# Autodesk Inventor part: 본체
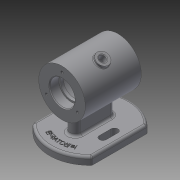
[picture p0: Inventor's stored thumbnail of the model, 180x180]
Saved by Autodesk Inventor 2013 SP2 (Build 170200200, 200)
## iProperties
Created: 2022-02
Part Number: 본체
Material: Generic
Document SubType Name: Modeling
Designer: a
Density: 1 g/cm^3
Mass: 183.424 g
Surface Area: 489.745 cm^2
Volume: 183.424 cm^3
Author: a
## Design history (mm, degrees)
sketch "스케치1"
  geometry: L1 (-36, 0)-(36, 0); L2 (-36, 16)-(-36, 30); L3 (-36, 30)-(36, 30); L4 (36, 30)-(36, 16); L5 (36, 16)-(24, 16); L6 (24, 16)-(24, 14); L7 (24, 14)-(20, 14); L8 (20, 14)-(20, 25); L9 (20, 25)-(-20, 25); L10 (-20, 25)-(-20, 14); L11 (-20, 14)-(-24, 14); L12 (-24, 14)-(-24, 16); L13 (-24, 16)-(-36, 16); 3 further points
  constraints: 26 end point, 9 parallel, 2 midpoint, 2 perpendicular, 1 coincident, 1 collinear, 1 horizontal, 1 vertical, 1 vertical alignment
  dimensions: "d0" = 72 distance of L1.start L1.end; "d1" = 28 diameter of L11 L1; "d2" = 28 diameter of L7 L1; "d3" = 60 diameter of L3 L1; "d4" = 50 diameter of L9 L1; "d5" = 32 diameter of L13 L1; "d6" = 32 diameter of L5 L1; "d7" = 12 distance of L12.end L2.start; "d8" = 40 distance of L8.end L9.end; "d9" = 12 distance of L4.end L5.end; "d10" = 72 distance from line of L4 point (-36, 23)
revolve "회전1" sketch "스케치1" stored, may be unused: angle "d11" = 90 deg
node "작업 평면1"
sketch "스케치2"
  geometry: L1 (36, 30)-(36, -30) reference; L2 (-36, 30)-(-36, -30) reference; L3 (36, -30)-(-36, -30) reference; L4 (35.496, -38)-(-35.496, -38); L5 (35.496, 38)-(-35.496, 38); A1 r 52 centre (0, 0) between (35.496, -38) and (35.496, 38); A2 r 52 centre (0, 0) between (-35.496, 38) and (-35.496, -38); 1 further point
  constraints: 4 end point, 4 point on circle, 2 centre point, 2 parallel, 1 coincident
  dimensions: "d14" = 76 distance between parallel lines of L5 L4; "d15" = 38 distance from line of L5 point (0, 0); "d16" = 52 radius of A2; "d17" = 52 radius of A1
extrude "돌출1" join sketch "스케치2" distance "d18" = 10; taper "d19" = 0 deg
sketch "스케치3"
  geometry: L1 (-26, -7)-(26, -7); L2 (26, -7)-(26, 7); L3 (26, 7)-(-26, 7); L4 (-26, 7)-(-26, -7); L5 (-26, -7)-(26, 7); L6 (26, -7)-(-26, 7); L7 (12, 19.5)-(-12, 19.5); L8 (-12, 19.5)-(-12, 28.5); L9 (-12, 28.5)-(12, 28.5); L10 (12, 28.5)-(12, 19.5); L11 (12, 19.5)-(-12, 28.5); L12 (-12, 19.5)-(12, 28.5); A1 r 52 centre (0, 0) between (-35.496, 38) and (-35.496, -38) reference; A2 r 52 centre (0, 0) between (35.496, -38) and (35.496, 38) reference; 5 further points
  constraints: 24 end point, 8 midpoint, 4 parallel, 2 horizontal, 2 perpendicular, 2 vertical alignment
  dimensions: "d20" = 52 distance of L3.end L2.end; "d21" = 14 distance of L2.end L1.end; "d22" = 24 distance of L8.end L9.end; "d23" = 9 distance of L7.end L8.end; "d24" = 24 distance of A1.centre point (0, 24)
extrude "돌출2" join sketch "스케치3" stored distance "d25" = 10; taper "d26" = 0 deg
extrude "돌출3" cut sketch "스케치3" stored distance "d27" = 10; taper "d28" = 0 deg
fillet "모깎기1" dims "d29" = 4.5
sketch "스케치4"
  geometry: L1 (0, 0)-(28.579, 16.5); L2 (0, 0)-(33, 0); 1 further point
  constraints: 4 end point, 1 coincident, 1 equal length, 1 horizontal
  dimensions: "d30" = 33 distance of L1.start L1.end; "d31" = 30 deg angle of L2 L1
node "작업 평면2"
sketch "스케치5"
  geometry: C1 r 8 at (0, 0); 1 further point
  constraints: 1 centre point, 1 coincident
  dimensions: "d32" = 16 diameter of C1
extrude "돌출4" join sketch "스케치5" stored distance "d34" = 10; taper "d35" = 0 deg
sketch "스케치6"
  geometry: C1 r 8 at (0, 0) reference; 1 further point
  constraints: 1 coincident
hole "구멍1" sketch "스케치6" at (0, 0) diameter "d36" = 8; stored, may be unused: countersink angle "d40" = 90 deg, drill point angle "d42" = 118 deg; dims "d37" = 6, "d38" = 4, "d39" = 2, "d41" = 8
sketch "스케치7"
  geometry: C1 r 30 at (0, 0) reference; 1 further point
  dimensions: "d43" = 23 distance of C1.centre point (0, 23)
hole "구멍2" sketch "스케치7" at (0, 23) diameter "d44" = 3.242; stored, may be unused: countersink angle "d48" = 90 deg, drill point angle "d50" = 118 deg; dims "d45" = 8, "d46" = 4, "d47" = 2, "d49" = 10
sketch "스케치8"
  geometry: C1 r 42.5 at (0, 0); A1 r 52 centre (0, 0) between (35.496, -38) and (35.496, 38) reference
  constraints: 1 centre point, 1 coincident, 1 other
  dimensions: "d54" = 85 diameter of C1
feature "엠보싱1" sketch "스케치8" dims "d55" = 0.5, "d56" = 0
fillet "모깎기2" dims "d57" = 0.3, "d58" = 3
chamfer "모따기1" distance "d59" = 1; stored, may be unused: second distance "d60" = 2, angle "d61" = 45 deg
fillet "모깎기3" dims "d65" = 7
fillet "모깎기4" dims "d66" = 3
fillet "모깎기5" dims "d67" = 3
fillet "모깎기6" dims "d68" = 3
fillet "모깎기7" dims "d69" = 1
fillet "모깎기8" dims "d70" = 1
node "솔리드1"
mirror "대칭1"
pattern_circular "원형 패턴1" dims angle "d52" = 360 deg
mirror "대칭2"
other parameters: "d12" = -62, "d13" = 104
